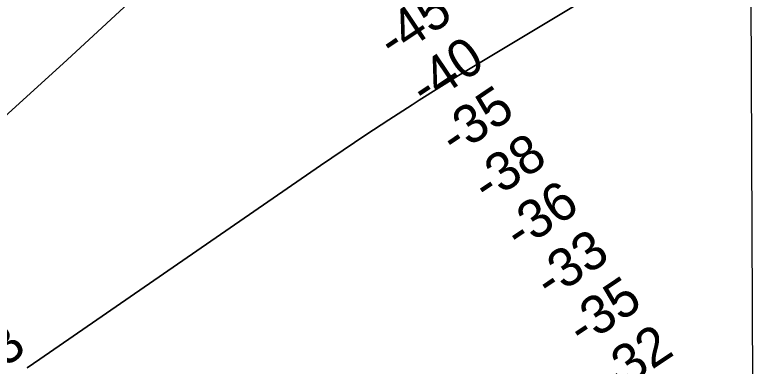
# Model space of a CAD drawing. Extents: x 3419139 to 3457078, y 540382 to 565875.
# Drawn here: x 3453623 to 3454925, y 549398 to 550011 of the extents above; entities that cross this region are included whole.
import ezdxf

# ---------------------------------------------------------------- set-up
doc = ezdxf.new("R2010")
doc.units = 0
for name, color, linetype in [('V-GRID-FRAM', 7, 'Continuous'), ('V-RIVR-RANG', 7, 'Continuous'), ('V-TOPO-DPTH', 7, 'Continuous'), ('V-TOPO-MINR', 7, 'Continuous')]:
    doc.layers.add(name, color=color, linetype=linetype)

msp = doc.modelspace()

# ---------------------------------------------------------------- linework, layer by layer
at = {"layer": 'V-GRID-FRAM'}
msp.add_lwpolyline([(3423200.9, 563955.1), (3454837.9, 564093.1), (3454925.2, 545910.2), (3423272.3, 545772.1), (3423200.9, 563955.1)], dxfattribs=at)
at = {"layer": 'V-TOPO-DPTH'}
msp.add_line((3454904.6, 550210.9), (3454910.3, 549010.6), dxfattribs=at)
for points in [[(3454901.6, 550821.8), (3454893, 550817.3), (3454879.1, 550809.3), (3454865.4, 550801.1), (3454301.1, 550449.9), (3454269.7, 550429.8), (3454238.8, 550409.1), (3454208.3, 550387.7), (3454178.3, 550365.6), (3454149.1, 550342.6), (3454120.4, 550318.9), (3454092.8, 550294), (3454065.8, 550268.4), (3453985.8, 550189.5), (3453918.9, 550124.3), (3453851.5, 550059.6), (3453783.2, 549995.8), (3453714.4, 549932.6), (3453489.7, 549728.6)], [(3453489.7, 549728.6), (3453714.4, 549932.6), (3453783.2, 549995.8), (3453851.5, 550059.6), (3453918.9, 550124.3), (3453985.8, 550189.5), (3454065.8, 550268.4), (3454092.8, 550294), (3454120.4, 550318.9), (3454149.1, 550342.6), (3454178.3, 550365.6), (3454208.3, 550387.7), (3454238.8, 550409.1), (3454269.7, 550429.8), (3454301.1, 550449.9), (3454865.4, 550801.1), (3454879.1, 550809.3), (3454893, 550817.3), (3454901.6, 550821.8)], [(3453644.6, 549395.2), (3453667, 549410.6), (3454155.7, 549748.1), (3454195.2, 549775.1), (3454235, 549801.8), (3454275, 549828.1), (3454315.3, 549854), (3454327.7, 549861.9), (3454362, 549883.6), (3454396.4, 549905.1), (3454431, 549926.3), (3454465.7, 549947.3), (3454904.6, 550210.9)], [(3454904.6, 550210.9), (3454465.7, 549947.3), (3454431, 549926.3), (3454396.4, 549905.1), (3454362, 549883.6), (3454327.7, 549861.9), (3454315.3, 549854), (3454275, 549828.1), (3454235, 549801.8), (3454195.2, 549775.1), (3454155.7, 549748.1), (3453667, 549410.6), (3453644.6, 549395.2)]]:
    msp.add_lwpolyline(points, dxfattribs=at)
at = {"layer": 'V-TOPO-MINR'}
for points in [[(3453489.7, 549728.6), (3453714.4, 549932.6), (3453783.2, 549995.8), (3453851.5, 550059.6), (3453918.9, 550124.3), (3453985.8, 550189.5), (3454065.8, 550268.4), (3454092.8, 550294), (3454120.4, 550318.9), (3454149.1, 550342.6), (3454178.3, 550365.6), (3454208.3, 550387.7), (3454238.8, 550409.1), (3454269.7, 550429.8), (3454301.1, 550449.9), (3454865.4, 550801.1), (3454879.1, 550809.3), (3454893, 550817.3), (3454901.6, 550821.8)], [(3453644.6, 549395.2), (3453667, 549410.6), (3454155.7, 549748.1), (3454195.2, 549775.1), (3454235, 549801.8), (3454275, 549828.1), (3454315.3, 549854), (3454327.7, 549861.9), (3454362, 549883.6), (3454396.4, 549905.1), (3454431, 549926.3), (3454465.7, 549947.3), (3454904.6, 550210.9)]]:
    msp.add_lwpolyline(points, dxfattribs=at)

# ---------------------------------------------------------------- texts
at = {"layer": 'V-RIVR-RANG'}
for s, rotation, p in [('-45', 33.8759, (3454282.4, 549932)), ('-40', 33.8759, (3454338.6, 549849.3)), ('-35', 33.8759, (3454390.4, 549763.6)), ('-38', 33.8759, (3454446.8, 549681)), ('-36', 33.8759, (3454502.8, 549598.2)), ('-33', 33.8759, (3454555.7, 549513.3)), ('-35', 33.8759, (3454612.5, 549431)), ('-43', 39.1152, (3453546, 549344.6)), ('-32', 33.8759, (3454667.2, 549347.2))]:
    msp.add_text(s, height=67, rotation=rotation, dxfattribs=at).set_placement(p)

doc.saveas('drawing.dxf')
